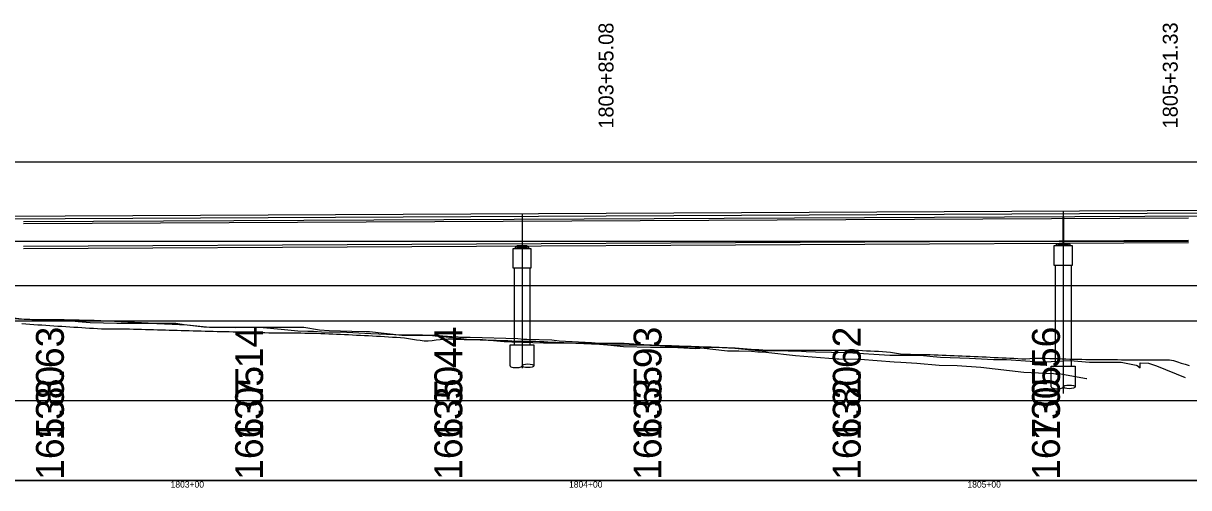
# Model space of a CAD drawing. Extents: x 2126510 to 2136144, y 865066 to 868066.
# Drawn here: x 2132861.8 to 2133154.3, y 867812.5 to 867929.2 of the extents above; entities that cross this region are included whole.
import ezdxf

# ---------------------------------------------------------------- set-up
doc = ezdxf.new("R2010")
doc.units = 0
for name, color, linetype in [('RD_DTM_BkLn1', 7, 'Continuous'), ('RD_EX_Bridge', 7, 'Continuous'), ('RD_EX_Conc_Curb', 7, 'Continuous'), ('RD_EX_GuardRail', 7, 'Continuous'), ('RD_EX_H2O', 7, 'Continuous'), ('RD_EX_Misc', 7, 'Continuous'), ('RD_EX_Misc_Golf_Cartpath', 7, 'Continuous'), ('RD_EX_UT', 7, 'Continuous'), ('RD_HC_Data', 7, 'Continuous'), ('RD_HC_txCode', 7, 'Continuous')]:
    doc.layers.add(name, color=color, linetype=linetype)

msp = doc.modelspace()

# ---------------------------------------------------------------- linework, layer by layer
at = {"layer": 'RD_DTM_BkLn1'}
for p, q in [((2132861.9, 867879.34), (2133296.65, 867881.51)), ((2132988.74, 867872.96), (2132985.24, 867872.96)), ((2132985.24, 867872.96), (2132985.24, 867872.63)), ((2132988.32, 867873.25), (2132985.65, 867873.25)), ((2132985.65, 867872.96), (2132988.32, 867872.96)), ((2132988.74, 867872.63), (2132988.74, 867872.96)), ((2133124.58, 867873.64), (2133121.08, 867873.64)), ((2133121.08, 867873.64), (2133121.08, 867873.31)), ((2133121.49, 867873.64), (2133124.16, 867873.64)), ((2133124.58, 867873.31), (2133124.58, 867873.64)), ((2133120.83, 867868.31), (2133120.83, 867843.07)), ((2133124.83, 867868.31), (2133124.83, 867843.07)), ((2132984.99, 867867.63), (2132984.99, 867848.38)), ((2132988.99, 867867.63), (2132988.99, 867848.38))]:
    msp.add_line(p, q, dxfattribs=at)
for points in [[(2132984.74, 867872.63), (2132989.24, 867872.63), (2132989.24, 867867.63), (2132984.74, 867867.63)], [(2133120.58, 867873.31), (2133125.08, 867873.31), (2133125.08, 867868.31), (2133120.58, 867868.31)]]:
    msp.add_lwpolyline(points, close=True, dxfattribs=at)
for points in [[(2132983.99, 867843.13), (2132983.99, 867848.38), (2132989.99, 867848.38), (2132989.99, 867843.13)], [(2133119.83, 867837.82), (2133119.83, 867843.07), (2133125.83, 867843.07), (2133125.83, 867837.82)]]:
    msp.add_lwpolyline(points, dxfattribs=at)
for centre in [(2132985.49, 867843.13), (2133121.33, 867837.82)]:
    msp.add_ellipse(centre, major_axis=(-1.5, 0), ratio=0.310397, start_param=0, end_param=3.141593, dxfattribs=at)
for centre in [(2132988.49, 867843.13), (2133124.33, 867837.82)]:
    msp.add_ellipse(centre, major_axis=(-1.5, 0), ratio=0.310397, dxfattribs=at)
at = {"layer": 'RD_EX_Bridge'}
for p, q in [((2133121.49, 867873.93), (2133121.49, 867873.64)), ((2133122.49, 867873.93), (2133122.49, 867873.64)), ((2133123.16, 867873.64), (2133123.16, 867873.93)), ((2133124.16, 867873.64), (2133124.16, 867873.93)), ((2132985.65, 867873.25), (2132985.65, 867872.96)), ((2132988.32, 867872.96), (2132988.32, 867873.25))]:
    msp.add_line(p, q, dxfattribs=at)
at = {"layer": 'RD_EX_Conc_Curb'}
msp.add_lwpolyline([(2132854.68, 867855.74), (2132862.03, 867854.85), (2132862.22, 867854.82), (2132862.82, 867854.82), (2132867.33, 867854.51), (2132871.68, 867854.54), (2132873.33, 867854.49), (2132875.58, 867854.25), (2132878.63, 867854), (2132885.32, 867853.87), (2132886.74, 867853.84), (2132896.65, 867853.84), (2132898.88, 867853.84), (2132900.1, 867853.83), (2132902.18, 867853.51), (2132908.56, 867852.79), (2132910.69, 867852.82), (2132919.23, 867852.82), (2132926.97, 867852.82), (2132932.25, 867852.82), (2132936.16, 867852.18), (2132938.59, 867851.98), (2132944.28, 867851.83), (2132947.82, 867851.74), (2132948.71, 867851.72), (2132956.81, 867850.86), (2132958.08, 867850.82), (2132960.97, 867850.79), (2132963.74, 867850.81), (2132966.63, 867850.49), (2132967.96, 867850.39), (2132968.13, 867850.37), (2132973.09, 867849.79), (2132977.1, 867849.71), (2132982.54, 867849.19), (2132984.41, 867849.17), (2132992.41, 867848.92), (2132994.09, 867848.91), (2132995.62, 867848.91), (2133003.33, 867848.82), (2133006.83, 867848.58), (2133012.45, 867848.01), (2133019.28, 867847.84), (2133024.54, 867847.82), (2133024.6, 867847.81), (2133030.54, 867847.49), (2133035.06, 867847.81), (2133035.62, 867847.82), (2133040.42, 867847.52), (2133048.13, 867846.81), (2133049.11, 867846.95), (2133050.34, 867846.95), (2133057.13, 867846.84), (2133058.27, 867846.71), (2133060.67, 867846.67), (2133068.68, 867846.5), (2133079.35, 867845.82), (2133082.13, 867845.81), (2133085.22, 867845.77), (2133086.91, 867845.76), (2133090.15, 867845.45), (2133092, 867845.26), (2133099.32, 867845.06), (2133105.33, 867844.68), (2133108.62, 867844.67), (2133115.74, 867844.22), (2133116.8, 867844.16), (2133118.21, 867844.15), (2133124.61, 867844.49), (2133129.43, 867844.06), (2133135.23, 867844.01), (2133137.34, 867844.07), (2133141.11, 867843.29), (2133141.38, 867843.17), (2133142.1, 867842.62), (2133142.14, 867843.85), (2133144.21, 867843.76), (2133146.22, 867843.12), (2133153.45, 867840.19)], dxfattribs=at)
at = {"layer": 'RD_EX_GuardRail'}
for p, q in [((2135251.98, 867894.32), (2130671.73, 867894.32)), ((2133154.24, 867874.32), (2130671.73, 867874.32)), ((2135251.98, 867854.32), (2130671.73, 867854.32)), ((2135251.98, 867834.32), (2130671.73, 867834.32)), ((2135251.98, 867814.32), (2130671.73, 867814.32))]:
    msp.add_line(p, q, dxfattribs=at)
at = {"layer": 'RD_EX_H2O'}
for points in [[(2132861.47, 867853.72), (2132862.47, 867853.65), (2132863.47, 867853.58), (2132864.47, 867853.52), (2132865.47, 867853.45), (2132866.47, 867853.38), (2132867.47, 867853.32), (2132868.47, 867853.25), (2132869.47, 867853.18), (2132870.47, 867853.12), (2132871.47, 867853.05), (2132872.47, 867852.98), (2132873.47, 867852.92), (2132874.47, 867852.85), (2132875.47, 867852.79), (2132876.47, 867852.72), (2132877.47, 867852.65), (2132878.47, 867852.59), (2132879.47, 867852.54), (2132880.47, 867852.49), (2132881.47, 867852.44), (2132882.47, 867852.39), (2132883.47, 867852.4), (2132884.47, 867852.4), (2132885.47, 867852.41), (2132886.47, 867852.42), (2132887.47, 867852.4), (2132888.47, 867852.37), (2132889.47, 867852.34), (2132890.47, 867852.32), (2132891.47, 867852.29)], [(2132891.47, 867852.29), (2132892.47, 867852.26), (2132893.47, 867852.23), (2132894.47, 867852.21), (2132895.47, 867852.18), (2132896.47, 867852.15), (2132897.47, 867852.13), (2132898.47, 867852.1), (2132899.47, 867852.07), (2132900.47, 867852.05), (2132901.47, 867852.02), (2132902.47, 867851.99), (2132903.47, 867851.96), (2132904.47, 867851.94), (2132905.47, 867851.91), (2132906.47, 867851.88), (2132907.47, 867851.86), (2132908.47, 867851.83), (2132909.47, 867851.8), (2132910.47, 867851.78), (2132911.47, 867851.75), (2132912.47, 867851.73), (2132913.47, 867851.7), (2132914.47, 867851.67), (2132915.47, 867851.65), (2132916.47, 867851.62), (2132917.47, 867851.59), (2132918.47, 867851.57), (2132919.47, 867851.54), (2132920.47, 867851.51), (2132921.47, 867851.49), (2132922.47, 867851.46), (2132923.47, 867851.44), (2132924.47, 867851.42), (2132925.47, 867851.41), (2132926.47, 867851.4), (2132927.47, 867851.4), (2132928.47, 867851.39), (2132929.47, 867851.38), (2132930.47, 867851.38), (2132931.47, 867851.37), (2132932.47, 867851.35), (2132933.47, 867851.33), (2132934.47, 867851.3), (2132935.47, 867851.28), (2132936.47, 867851.25), (2132937.47, 867851.2), (2132938.47, 867851.16), (2132939.47, 867851.12), (2132940.47, 867851.08), (2132941.47, 867851.03), (2132942.47, 867850.99), (2132943.47, 867850.95), (2132944.47, 867850.9), (2132945.47, 867850.86), (2132946.47, 867850.82), (2132947.47, 867850.76), (2132948.47, 867850.7), (2132949.47, 867850.64), (2132950.47, 867850.59), (2132951.47, 867850.53), (2132952.47, 867850.47), (2132953.47, 867850.41), (2132954.47, 867850.35), (2132955.47, 867850.29), (2132956.47, 867850.23), (2132957.47, 867850.11), (2132958.47, 867849.97), (2132959.47, 867849.82), (2132960.47, 867849.68), (2132961.47, 867849.53), (2132962.47, 867849.39), (2132963.47, 867849.42), (2132964.47, 867849.51), (2132965.47, 867849.61), (2132966.47, 867849.7), (2132967.47, 867849.8), (2132968.47, 867849.89), (2132969.47, 867849.86), (2132970.47, 867849.83), (2132971.47, 867849.8), (2132972.47, 867849.77), (2132973.47, 867849.75), (2132974.47, 867849.72), (2132975.47, 867849.69), (2132976.47, 867849.66), (2132977.47, 867849.63), (2132978.47, 867849.6), (2132979.47, 867849.57), (2132980.47, 867849.55), (2132981.47, 867849.52), (2132982.47, 867849.49), (2132983.47, 867849.46), (2132984.47, 867849.43), (2132985.47, 867849.35), (2132986.47, 867849.33), (2132987.47, 867849.32), (2132988.47, 867849.31), (2132989.47, 867849.31), (2132990.47, 867849.29), (2132991.47, 867849.24)], [(2132991.47, 867849.24), (2132992.47, 867849.19), (2132993.47, 867849.15), (2132994.47, 867849.1), (2132995.47, 867849.06), (2132996.47, 867849.01), (2132997.47, 867848.97), (2132998.47, 867848.92), (2132999.47, 867848.87), (2133000.47, 867848.83), (2133001.47, 867848.78), (2133002.47, 867848.74), (2133003.47, 867848.69), (2133004.47, 867848.65), (2133005.47, 867848.6), (2133006.47, 867848.55), (2133007.47, 867848.51), (2133008.47, 867848.46), (2133009.47, 867848.42), (2133010.47, 867848.41), (2133011.47, 867848.4), (2133012.47, 867848.39), (2133013.47, 867848.38), (2133014.47, 867848.38), (2133015.47, 867848.37), (2133016.47, 867848.37), (2133017.47, 867848.36), (2133018.47, 867848.36), (2133019.47, 867848.36), (2133020.47, 867848.33), (2133021.47, 867848.3), (2133022.47, 867848.26), (2133023.47, 867848.23), (2133024.47, 867848.19), (2133025.47, 867848.16), (2133026.47, 867848.12), (2133027.47, 867848.09), (2133028.47, 867848.05), (2133029.47, 867848.02), (2133030.47, 867847.98), (2133031.47, 867847.95), (2133032.47, 867847.92), (2133033.47, 867847.88), (2133034.47, 867847.85), (2133035.47, 867847.81), (2133036.47, 867847.78), (2133037.47, 867847.74), (2133038.47, 867847.71), (2133039.47, 867847.67), (2133040.47, 867847.64), (2133041.47, 867847.58), (2133042.47, 867847.46), (2133043.47, 867847.35), (2133044.47, 867847.29), (2133045.47, 867847.24), (2133046.47, 867847.18), (2133047.47, 867847.13), (2133048.47, 867847.07), (2133049.47, 867847.04), (2133050.47, 867847.04), (2133051.47, 867847.04), (2133052.47, 867847.04), (2133053.47, 867847.04), (2133054.47, 867847.04), (2133055.47, 867847.04), (2133056.47, 867847.03), (2133057.47, 867847.03), (2133058.47, 867847.03), (2133059.47, 867847.03), (2133060.47, 867847.03), (2133061.47, 867847.03), (2133062.47, 867847.03), (2133063.47, 867847.03), (2133064.47, 867847.03), (2133065.47, 867847.03), (2133066.47, 867847.03), (2133067.47, 867847.02), (2133068.47, 867847.02), (2133069.47, 867847.02), (2133070.47, 867847.02), (2133071.47, 867847.01), (2133072.47, 867846.96), (2133073.47, 867846.92), (2133074.47, 867846.87), (2133075.47, 867846.82), (2133076.47, 867846.77), (2133077.47, 867846.72), (2133078.47, 867846.66), (2133079.47, 867846.51), (2133080.47, 867846.37), (2133081.47, 867846.22), (2133082.47, 867846.08), (2133083.47, 867846.03), (2133084.47, 867846.02), (2133085.47, 867846), (2133086.47, 867845.98), (2133087.47, 867845.97), (2133088.47, 867845.95), (2133089.47, 867845.93), (2133090.47, 867845.9), (2133091.47, 867845.86)], [(2133091.47, 867845.86), (2133092.47, 867845.82), (2133093.47, 867845.78), (2133094.47, 867845.74), (2133095.47, 867845.7), (2133096.47, 867845.66), (2133097.47, 867845.62), (2133098.47, 867845.58), (2133099.47, 867845.53), (2133100.47, 867845.48), (2133101.47, 867845.43), (2133102.47, 867845.39), (2133103.47, 867845.34), (2133104.47, 867845.29), (2133105.47, 867845.24), (2133106.47, 867845.19), (2133107.47, 867845.15), (2133108.47, 867845.1), (2133109.47, 867845.05), (2133110.47, 867845), (2133111.47, 867844.95), (2133112.47, 867844.9), (2133113.47, 867844.88), (2133114.47, 867844.95), (2133115.47, 867845.01), (2133116.47, 867845.07), (2133117.47, 867845.03), (2133118.47, 867845), (2133119.47, 867844.97), (2133120.47, 867844.95), (2133121.47, 867844.92), (2133122.47, 867844.89), (2133123.47, 867844.86), (2133124.47, 867844.83), (2133125.47, 867844.81), (2133126.47, 867844.78), (2133127.47, 867844.75), (2133128.47, 867844.72), (2133129.47, 867844.7), (2133130.47, 867844.7), (2133131.47, 867844.69), (2133132.47, 867844.69), (2133133.47, 867844.68), (2133134.47, 867844.68), (2133135.47, 867844.67), (2133136.47, 867844.67), (2133137.47, 867844.66), (2133138.47, 867844.66), (2133139.47, 867844.65), (2133140.47, 867844.65), (2133141.47, 867844.64), (2133142.47, 867844.64), (2133143.47, 867844.63), (2133144.47, 867844.63), (2133145.47, 867844.62), (2133146.47, 867844.62), (2133147.47, 867844.61), (2133148.47, 867844.61), (2133149.47, 867844.59), (2133150.47, 867844.45), (2133151.47, 867844.14), (2133152.47, 867843.82), (2133153.47, 867843.5), (2133154.47, 867843.18)]]:
    msp.add_lwpolyline(points, dxfattribs=at)
at = {"layer": 'RD_EX_Misc'}
for p, q in [((2132116.01, 867877.03), (2133296.65, 867882.93)), ((2131523, 867814.32), (2135677.25, 867814.32))]:
    msp.add_line(p, q, dxfattribs=at)
msp.add_lwpolyline([(2131430.13, 867814.32), (2131430.13, 867863.32), (2136143.96, 867863.32)], dxfattribs=at)
at = {"layer": 'RD_EX_Misc_Golf_Cartpath'}
msp.add_lwpolyline([(2132851.98, 867855.17), (2132866.34, 867854.75), (2132872.06, 867854.76), (2132879.58, 867854.57), (2132893.17, 867853.92), (2132894.26, 867853.86), (2132894.35, 867853.86), (2132894.68, 867853.81), (2132895.3, 867853.79), (2132902.97, 867853.42), (2132907.12, 867852.94), (2132907.41, 867852.94), (2132907.8, 867852.93), (2132915.11, 867852.78), (2132919.37, 867852.8), (2132922.06, 867852.75), (2132926.54, 867852.31), (2132930.76, 867851.89), (2132933.2, 867851.84), (2132934.26, 867851.81), (2132934.64, 867851.81), (2132936.69, 867851.68), (2132942.99, 867851.55), (2132949.06, 867851.25), (2132954.99, 867851.01), (2132962.01, 867850.87), (2132964.98, 867850.82), (2132969.36, 867850.48), (2132970.95, 867850.36), (2132971.3, 867850.35), (2132973.94, 867850.31), (2132985.93, 867849.95), (2132987.34, 867849.85), (2132987.51, 867849.82), (2132988.17, 867849.8), (2132994.51, 867849.62), (2132996.33, 867849.41), (2133004.44, 867848.98), (2133006.37, 867848.82), (2133006.68, 867848.82), (2133007.36, 867848.82), (2133009.58, 867848.77), (2133012.6, 867848.77), (2133017.54, 867848.47), (2133019.09, 867848.32), (2133020.31, 867848.31), (2133025.51, 867848), (2133027.96, 867847.83), (2133029.32, 867847.64), (2133029.65, 867847.61), (2133031.94, 867847.66), (2133038.56, 867846.85), (2133041.37, 867846.87), (2133044.56, 867846.82), (2133046.14, 867846.66), (2133046.48, 867846.65), (2133048.17, 867846.55), (2133055.66, 867845.74), (2133066.06, 867844.9), (2133066.48, 867844.87), (2133071.89, 867844.75), (2133080.42, 867844.11), (2133082.07, 867844.01), (2133086.09, 867843.76), (2133091.69, 867843.26), (2133096.24, 867843.18), (2133102.17, 867842.79), (2133112.91, 867841.56), (2133122.19, 867841.13), (2133128.17, 867840.03), (2133128.68, 867839.94), (2133128.75, 867839.92)], dxfattribs=at)
at = {"layer": 'RD_EX_UT'}
msp.add_line((2132116.01, 867876.33), (2133296.65, 867882.24), dxfattribs=at)
at = {"layer": 'RD_HC_Data'}
for p, q in [((2132986.99, 867881.39), (2132986.99, 867842.55)), ((2133122.83, 867882.06), (2133122.83, 867836.2))]:
    msp.add_line(p, q, dxfattribs=at)
at = {"layer": 'RD_HC_txCode'}
for p, q in [((2132861.9, 867878.84), (2133154.24, 867880.3)), ((2133122.74, 867880.64), (2133122.74, 867873.93)), ((2133122.91, 867880.64), (2133122.91, 867873.93)), ((2132861.9, 867873.21), (2133154.24, 867874.67)), ((2132861.9, 867872.63), (2133154.24, 867874.09))]:
    msp.add_line(p, q, dxfattribs=at)

# ---------------------------------------------------------------- texts
at = {"layer": 'RD_EX_Misc'}
for s, height, p in [('1803+85.08', 3.75, (2133009.95, 867902.7)), ('1805+31.33', 3.75, (2133151.56, 867902.76)), ('138.63', 7, (2132872, 867824.32)), ('137.14', 7, (2132922, 867824.32)), ('135.44', 7, (2132972, 867824.32)), ('133.93', 7, (2133022, 867824.32)), ('132.62', 7, (2133072, 867824.32)), ('130.56', 7, (2133122, 867824.32)), ('165.80', 7, (2132872, 867814.47)), ('166.05', 7, (2132922, 867814.47)), ('166.30', 7, (2132972, 867814.47)), ('166.55', 7, (2133022, 867814.47)), ('166.80', 7, (2133072, 867814.47)), ('167.05', 7, (2133122, 867814.47))]:
    msp.add_text(s, height=height, rotation=90, dxfattribs=at).set_placement(p)
for s, p in [('1803+00', (2132898.79, 867812.52)), ('1804+00', (2132998.79, 867812.52)), ('1805+00', (2133098.79, 867812.52))]:
    msp.add_text(s, height=1.6, dxfattribs=at).set_placement(p)

doc.saveas('drawing.dxf')
